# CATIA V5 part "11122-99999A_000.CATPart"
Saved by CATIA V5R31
Part number: 11122-99999A_000
Nomenclature: TRIM,FRONT PILLAR,L
Source: Unknown
Property "部品番号(A社)": "11122-99999"
Property "部品名称(A社)": "TRIM,FRONT PILLAR,L"
Property "Version(A社)": "001"
Property "材質(A社)": "PP-JAMA9"
Property "板厚": "2"
Bounding box of the stored display mesh (mm): x 514.362 to 596.348, y 913.531 to 1307.189, z 734.649 to 1101.166
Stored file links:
  \\solize.local\damia\dept\DDE_Design\10_order\2305701_JAMA_変換検証STEP3_お手本モデル作成\work\07_スズキ_樹脂\10_CATIA_V5\231211\240117\11122-99999A_000.CATPart
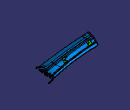
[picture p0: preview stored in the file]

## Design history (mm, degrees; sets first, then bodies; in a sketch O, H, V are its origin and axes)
Set1
  Point1 "CARTESIAN_POINT #6014": stored without definition
  Line1 "LINE #5264": stored without definition
  Line2 "LINE #5265": stored without definition
  Line3 "LINE #5266": stored without definition
  Line4 "LINE #5267": stored without definition
  Line5 "LINE #5268": stored without definition
  Line6 "LINE #5269": stored without definition
  Line7 "LINE #5270": stored without definition
  Line8 "LINE #5271": stored without definition
  Line9 "LINE #5272": stored without definition
  Line10 "LINE #5273": stored without definition
  Line11 "LINE #5274": stored without definition
  Line12 "LINE #5275": stored without definition
  Line13 "LINE #5276": stored without definition
  Line14 "LINE #5277": stored without definition
  Line15 "LINE #5278": stored without definition
  Line16 "LINE #5279": stored without definition
  Line17 "LINE #5280": stored without definition
  Line18 "LINE #5281": stored without definition
  Circle1 "CIRCLE #5205": stored without definition
Body1 "MANIFOLD_SOLID_BREP #199" (main body)
  Solid1: solid without history
Body2 "MANIFOLD_SOLID_BREP #200"
  Solid2: solid without history
Body3 "MANIFOLD_SOLID_BREP #201"
  Solid3: solid without history
Body4 "MANIFOLD_SOLID_BREP #202"
  Solid4: solid without history
Body5 "MANIFOLD_SOLID_BREP #203"
  Solid5: solid without history
Body6 "MANIFOLD_SOLID_BREP #204"
  Solid6: solid without history
Body7 "MANIFOLD_SOLID_BREP #205"
  Solid7: solid without history
Body8 "MANIFOLD_SOLID_BREP #206"
  Solid8: solid without history
Body9 "MANIFOLD_SOLID_BREP #207"
  Solid9: solid without history
Body10 "MANIFOLD_SOLID_BREP #208"
  Solid10: solid without history
Body11 "MANIFOLD_SOLID_BREP #209"
  Solid11: solid without history
Body12 "MANIFOLD_SOLID_BREP #210"
  Solid12: solid without history
Body13 "MANIFOLD_SOLID_BREP #211"
  Solid13: solid without history
Body14 "MANIFOLD_SOLID_BREP #212"
  Solid14: solid without history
